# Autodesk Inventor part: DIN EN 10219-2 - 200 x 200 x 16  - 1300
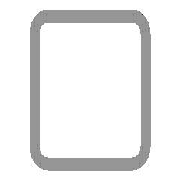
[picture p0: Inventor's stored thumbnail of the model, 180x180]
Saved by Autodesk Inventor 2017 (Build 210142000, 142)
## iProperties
Created: 2016-02
Part Number: DIN EN 10219-2 - 200 x 200 x 16  - 1300
Material: Steel, Mild
Description: Cold formed welded structural hollow sections of non-alloy and fine grain structural steel
Document SubType Name: Modeling
Standard: DIN
Designer: iusti
Standard Revision: 2006-07
Standards Organization: DIN
Language: en-US
Size Designation: 200 x 200 x 16
Categories: <MemberInstance><Categories><Category DisplayName="Structural Shapes" InternalName="089c4875-fa83-4c05-b084-43b9cc11f5ed" Mnemonic="GRDR"><CategoryParameter Dis
Stock Number: 200 x 200 x 16
Mass: 108961 g
Surface Area: 17564.1 cm^2
Volume: 13880.4 cm^3
Density: 7.85 g/cm^3
Appearance: Semi-Polished
G_L: 1300.000 mm
G_W: 200.000 mm
G_H: 200.000 mm
+9B96A9D1-53DA-4299-ADB7-BA59D95C451C+CUTDETAIL1: Cut
+EC60967C-127F-4733-B979-3413A57744B4+CUTDETAIL2: Cut
IsCustomPart: 1
_CCFamilyMember: 103
_CCFamilyDisplayName: DIN EN 10219-2 (Square Hollow Section - Cold Formed) - Cold formed welded structural hollow sections of non-alloy and fine grain structural steel
_FrameMemberDoc: Frame Member File
_Version: 15.0.0
_GetPNFromCC: 1
Author: iusti
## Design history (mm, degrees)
node "Start plane"
node "End plane"
sketch "Sketch"
  geometry: L1 (-100, -52)-(-100, 52); L2 (-52, 100)-(52, 100); L3 (100, 52)-(100, -52); L4 (52, -100)-(-52, -100); L5 (-52, 84)-(52, 84); L6 (84, 52)-(84, -52); L7 (52, -84)-(-52, -84); L8 (-84, -52)-(-84, 52); L9 (0, 153.918)-(0, -153.918) reference; L10 (-153.918, 0)-(153.918, 0) reference; A1 r 48 centre (-52, -52) between (-100, -52) and (-52, -100); A2 r 48 centre (-52, 52) between (-52, 100) and (-100, 52); A3 r 48 centre (52, 52) between (100, 52) and (52, 100); A4 r 48 centre (52, -52) between (52, -100) and (100, -52); A5 r 32 centre (-52, 52) between (-52, 84) and (-84, 52); A6 r 32 centre (52, 52) between (84, 52) and (52, 84); A7 r 32 centre (52, -52) between (52, -84) and (84, -52); A8 r 32 centre (-52, -52) between (-84, -52) and (-52, -84)
  constraints: 16 end point, 16 point on circle, 8 centre point, 8 tangent, 4 parallel, 3 equal radius, 2 perpendicular, 7 other
  dimensions: "d7" = 48 radius of A1 (= G_IR); "d10" = 200 distance between parallel lines of L2 L4 (= G_H); "d11" = 200 distance between parallel lines of L1 L3 (= G_W); "d12" = 16 distance between parallel lines of L3 L6 (= G_T); "d15" = 100 distance between parallel lines of L2 L10 (= 0.5 x d10); "d16" = 100 distance between parallel lines of L9 L3 (= 0.5 x d11)
extrude "Body" new body sketch "Sketch" stored distance "d3" = 1300 (= G_L); taper "d4" = 0 deg
node "Driven Length"
  sketch "Sketch3"
    geometry: L1 (0, 0)-(10, 0) reference
    constraints: 2 end point, 1 horizontal
  workplane "Work Plane3"
  sketch "Sketch4"
    geometry: L1 (-2, 100)-(12, 100) reference; L2 (-2, 1400)-(12, 1400) reference
    dimensions: "d18" = 1300 distance between parallel lines of L1 L2 (derived)
workplane "Work Plane4"
split "Split1"
workplane "Work Plane5"
split "Split2"
body "Solid1"
other parameters: "G_W" = 200 [user parameter; used in 1 equation term], "G_H" = 200 [user parameter; used in 1 equation term], "G_T" = 16 [user parameter; used in 1 equation term], "G_IR" = 48 [user parameter; used in 1 equation term], "G_L" = 1300 (= d18) [user parameter; used in 1 equation term], "d17" = 90 deg
